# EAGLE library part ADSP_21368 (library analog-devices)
SHARC Processor Auto generated by make-symbol-device-package-bsdl.ulp Rev. 33 Source: 78445023821368_256ballSBGA_bsdl_PrA_0206.txt http://www.analog.com/static/imported-files/data_sheets/ADSP-21367_21368_21369.pdf
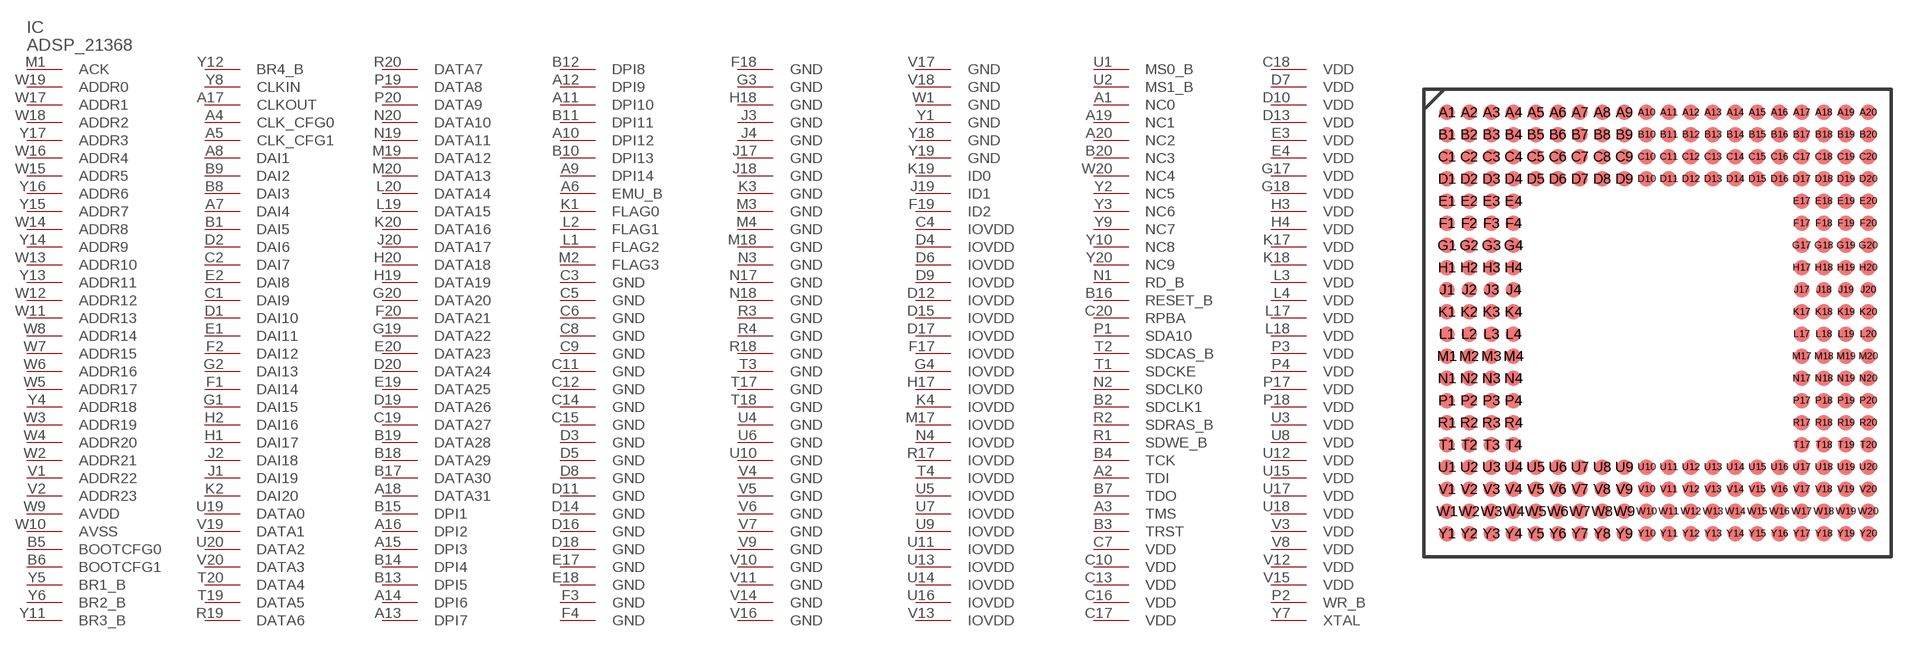
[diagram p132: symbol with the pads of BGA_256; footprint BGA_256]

Designator prefix IC

## ADSP_21368 (OC_FARNELL: 1776206; OC_NEWARK: unknown)  [BGA_256]
A1  NC0  pas
A2  TDI  in
A3  TMS  in
A4  CLK_CFG0  in
A5  CLK_CFG1  in
A6  EMU_B  out
A7  DAI4
A8  DAI1
A9  DPI14
A10  DPI12
A11  DPI10
A12  DPI9
A13  DPI7
A14  DPI6
A15  DPI3
A16  DPI2
A17  CLKOUT  out
A18  DATA31
A19  NC1  pas
A20  NC2  pas
B1  DAI5
B2  SDCLK1
B3  TRST  in
B4  TCK  in
B5  BOOTCFG0  in
B6  BOOTCFG1  in
B7  TDO  out
B8  DAI3
B9  DAI2
B10  DPI13
B11  DPI11
B12  DPI8
B13  DPI5
B14  DPI4
B15  DPI1
B16  RESET_B  in
B17  DATA30
B18  DATA29
B19  DATA28
B20  NC3  pas
C1  DAI9
C2  DAI7
C3  GND  pwr
C4  IOVDD  pwr
C5  GND  pwr
C6  GND  pwr
C7  VDD  pwr
C8  GND  pwr
C9  GND  pwr
C10  VDD  pwr
C11  GND  pwr
C12  GND  pwr
C13  VDD  pwr
C14  GND  pwr
C15  GND  pwr
C16  VDD  pwr
C17  VDD  pwr
C18  VDD  pwr
C19  DATA27
C20  RPBA  in
D1  DAI10
D2  DAI6
D3  GND  pwr
D4  IOVDD  pwr
D5  GND  pwr
D6  IOVDD  pwr
D7  VDD  pwr
D8  GND  pwr
D9  IOVDD  pwr
D10  VDD  pwr
D11  GND  pwr
D12  IOVDD  pwr
D13  VDD  pwr
D14  GND  pwr
D15  IOVDD  pwr
D16  GND  pwr
D17  IOVDD  pwr
D18  GND  pwr
D19  DATA26
D20  DATA24
E1  DAI11
E2  DAI8
E3  VDD  pwr
E4  VDD  pwr
E17  GND  pwr
E18  GND  pwr
E19  DATA25
E20  DATA23
F1  DAI14
F2  DAI12
F3  GND  pwr
F4  GND  pwr
F17  IOVDD  pwr
F18  GND  pwr
F19  ID2  in
F20  DATA21
G1  DAI15
G2  DAI13
G3  GND  pwr
G4  IOVDD  pwr
G17  VDD  pwr
G18  VDD  pwr
G19  DATA22
G20  DATA20
H1  DAI17
H2  DAI16
H3  VDD  pwr
H4  VDD  pwr
H17  IOVDD  pwr
H18  GND  pwr
H19  DATA19
H20  DATA18
J1  DAI19
J2  DAI18
J3  GND  pwr
J4  GND  pwr
J17  GND  pwr
J18  GND  pwr
J19  ID1  in
J20  DATA17
K1  FLAG0
K2  DAI20
K3  GND  pwr
K4  IOVDD  pwr
K17  VDD  pwr
K18  VDD  pwr
K19  ID0  in
K20  DATA16
L1  FLAG2
L2  FLAG1
L3  VDD  pwr
L4  VDD  pwr
L17  VDD  pwr
L18  VDD  pwr
L19  DATA15
L20  DATA14
M1  ACK  in
M2  FLAG3
M3  GND  pwr
M4  GND  pwr
M17  IOVDD  pwr
M18  GND  pwr
M19  DATA12
M20  DATA13
N1  RD_B  out
N2  SDCLK0
N3  GND  pwr
N4  IOVDD  pwr
N17  GND  pwr
N18  GND  pwr
N19  DATA11
N20  DATA10
P1  SDA10  out
P2  WR_B  out
P3  VDD  pwr
P4  VDD  pwr
P17  VDD  pwr
P18  VDD  pwr
P19  DATA8
P20  DATA9
R1  SDWE_B  out
R2  SDRAS_B  out
R3  GND  pwr
R4  GND  pwr
R17  IOVDD  pwr
R18  GND  pwr
R19  DATA6
R20  DATA7
T1  SDCKE  out
T2  SDCAS_B  out
T3  GND  pwr
T4  IOVDD  pwr
T17  GND  pwr
T18  GND  pwr
T19  DATA5
T20  DATA4
U1  MS0_B  out
U2  MS1_B  out
U3  VDD  pwr
U4  GND  pwr
U5  IOVDD  pwr
U6  GND  pwr
U7  IOVDD  pwr
U8  VDD  pwr
U9  IOVDD  pwr
U10  GND  pwr
U11  IOVDD  pwr
U12  VDD  pwr
U13  IOVDD  pwr
U14  IOVDD  pwr
U15  VDD  pwr
U16  IOVDD  pwr
U17  VDD  pwr
U18  VDD  pwr
U19  DATA0
U20  DATA2
V1  ADDR22  out
V2  ADDR23  out
V3  VDD  pwr
V4  GND  pwr
V5  GND  pwr
V6  GND  pwr
V7  GND  pwr
V8  VDD  pwr
V9  GND  pwr
V10  GND  pwr
V11  GND  pwr
V12  VDD  pwr
V13  IOVDD  pwr
V14  GND  pwr
V15  VDD  pwr
V16  GND  pwr
V17  GND  pwr
V18  GND  pwr
V19  DATA1
V20  DATA3
W1  GND  pwr
W2  ADDR21  out
W3  ADDR19  out
W4  ADDR20  out
W5  ADDR17  out
W6  ADDR16  out
W7  ADDR15  out
W8  ADDR14  out
W9  AVDD  pwr
W10  AVSS  pwr
W11  ADDR13  out
W12  ADDR12  out
W13  ADDR10  out
W14  ADDR8  out
W15  ADDR5  out
W16  ADDR4  out
W17  ADDR1  out
W18  ADDR2  out
W19  ADDR0  out
W20  NC4  pas
Y1  GND  pwr
Y2  NC5  pas
Y3  NC6  pas
Y4  ADDR18  out
Y5  BR1_B
Y6  BR2_B
Y7  XTAL  out
Y8  CLKIN  in
Y9  NC7  pas
Y10  NC8  pas
Y11  BR3_B
Y12  BR4_B
Y13  ADDR11  out
Y14  ADDR9  out
Y15  ADDR7  out
Y16  ADDR6  out
Y17  ADDR3  out
Y18  GND  pwr
Y19  GND  pwr
Y20  NC9  pas

## Footprint BGA_256 (pad centres in mm)
256-Ball Ball Grid Array, Thermally Enhanced BGA_ED Auto generated by make-symbol-device-package-bsdl.ulp Rev. 33 Source: 78445023821368_256ballSBGA_bsdl_PrA_0206.txt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
smd 0.9 x 0.9: A1 -12.065,12.065; A2 -10.795,12.065; A3 -9.525,12.065; A4 -8.255,12.065; A5 -6.985,12.065; A6 -5.715,12.065; A7 -4.445,12.065; A8 -3.175,12.065; A9 -1.905,12.065; A10 -0.635,12.065; A11 0.635,12.065; A12 1.905,12.065; A13 3.175,12.065; A14 4.445,12.065; A15 5.715,12.065; A16 6.985,12.065; A17 8.255,12.065; A18 9.525,12.065; A19 10.795,12.065; A20 12.065,12.065; B1 -12.065,10.795; B2 -10.795,10.795; B3 -9.525,10.795; B4 -8.255,10.795; B5 -6.985,10.795; B6 -5.715,10.795; B7 -4.445,10.795; B8 -3.175,10.795; B9 -1.905,10.795; B10 -0.635,10.795; B11 0.635,10.795; B12 1.905,10.795; B13 3.175,10.795; B14 4.445,10.795; B15 5.715,10.795; B16 6.985,10.795; B17 8.255,10.795; B18 9.525,10.795; B19 10.795,10.795; B20 12.065,10.795; C1 -12.065,9.525; C2 -10.795,9.525; C3 -9.525,9.525; C4 -8.255,9.525; C5 -6.985,9.525; C6 -5.715,9.525; C7 -4.445,9.525; C8 -3.175,9.525; C9 -1.905,9.525; C10 -0.635,9.525; C11 0.635,9.525; C12 1.905,9.525; C13 3.175,9.525; C14 4.445,9.525; C15 5.715,9.525; C16 6.985,9.525; C17 8.255,9.525; C18 9.525,9.525; C19 10.795,9.525; C20 12.065,9.525; D1 -12.065,8.255; D2 -10.795,8.255; D3 -9.525,8.255; D4 -8.255,8.255; D5 -6.985,8.255; D6 -5.715,8.255; D7 -4.445,8.255; D8 -3.175,8.255; D9 -1.905,8.255; D10 -0.635,8.255; D11 0.635,8.255; D12 1.905,8.255; D13 3.175,8.255; D14 4.445,8.255; D15 5.715,8.255; D16 6.985,8.255; D17 8.255,8.255; D18 9.525,8.255; D19 10.795,8.255; D20 12.065,8.255; E1 -12.065,6.985; E2 -10.795,6.985; E3 -9.525,6.985; E4 -8.255,6.985; E17 8.255,6.985; E18 9.525,6.985; E19 10.795,6.985; E20 12.065,6.985; F1 -12.065,5.715; F2 -10.795,5.715; F3 -9.525,5.715; F4 -8.255,5.715; F17 8.255,5.715; F18 9.525,5.715; F19 10.795,5.715; F20 12.065,5.715; G1 -12.065,4.445; G2 -10.795,4.445; G3 -9.525,4.445; G4 -8.255,4.445; G17 8.255,4.445; G18 9.525,4.445; G19 10.795,4.445; G20 12.065,4.445; H1 -12.065,3.175; H2 -10.795,3.175; H3 -9.525,3.175; H4 -8.255,3.175; H17 8.255,3.175; H18 9.525,3.175; H19 10.795,3.175; H20 12.065,3.175; J1 -12.065,1.905; J2 -10.795,1.905; J3 -9.525,1.905; J4 -8.255,1.905; J17 8.255,1.905; J18 9.525,1.905; J19 10.795,1.905; J20 12.065,1.905; K1 -12.065,0.635; K2 -10.795,0.635; K3 -9.525,0.635; K4 -8.255,0.635; K17 8.255,0.635; K18 9.525,0.635; K19 10.795,0.635; K20 12.065,0.635; L1 -12.065,-0.635; L2 -10.795,-0.635; L3 -9.525,-0.635; L4 -8.255,-0.635; L17 8.255,-0.635; L18 9.525,-0.635; L19 10.795,-0.635; L20 12.065,-0.635; M1 -12.065,-1.905; M2 -10.795,-1.905; M3 -9.525,-1.905; M4 -8.255,-1.905; M17 8.255,-1.905; M18 9.525,-1.905; M19 10.795,-1.905; M20 12.065,-1.905; N1 -12.065,-3.175; N2 -10.795,-3.175; N3 -9.525,-3.175; N4 -8.255,-3.175; N17 8.255,-3.175; N18 9.525,-3.175; N19 10.795,-3.175; N20 12.065,-3.175; P1 -12.065,-4.445; P2 -10.795,-4.445; P3 -9.525,-4.445; P4 -8.255,-4.445; P17 8.255,-4.445; P18 9.525,-4.445; P19 10.795,-4.445; P20 12.065,-4.445; R1 -12.065,-5.715; R2 -10.795,-5.715; R3 -9.525,-5.715; R4 -8.255,-5.715; R17 8.255,-5.715; R18 9.525,-5.715; R19 10.795,-5.715; R20 12.065,-5.715; T1 -12.065,-6.985; T2 -10.795,-6.985; T3 -9.525,-6.985; T4 -8.255,-6.985; T17 8.255,-6.985; T18 9.525,-6.985; T19 10.795,-6.985; T20 12.065,-6.985; U1 -12.065,-8.255; U2 -10.795,-8.255; U3 -9.525,-8.255; U4 -8.255,-8.255; U5 -6.985,-8.255; U6 -5.715,-8.255; U7 -4.445,-8.255; U8 -3.175,-8.255; U9 -1.905,-8.255; U10 -0.635,-8.255; U11 0.635,-8.255; U12 1.905,-8.255; U13 3.175,-8.255; U14 4.445,-8.255; U15 5.715,-8.255; U16 6.985,-8.255; U17 8.255,-8.255; U18 9.525,-8.255; U19 10.795,-8.255; U20 12.065,-8.255; V1 -12.065,-9.525; V2 -10.795,-9.525; V3 -9.525,-9.525; V4 -8.255,-9.525; V5 -6.985,-9.525; V6 -5.715,-9.525; V7 -4.445,-9.525; V8 -3.175,-9.525; V9 -1.905,-9.525; V10 -0.635,-9.525; V11 0.635,-9.525; V12 1.905,-9.525; V13 3.175,-9.525; V14 4.445,-9.525; V15 5.715,-9.525; V16 6.985,-9.525; V17 8.255,-9.525; V18 9.525,-9.525; V19 10.795,-9.525; V20 12.065,-9.525; W1 -12.065,-10.795; W2 -10.795,-10.795; W3 -9.525,-10.795; W4 -8.255,-10.795; W5 -6.985,-10.795; W6 -5.715,-10.795; W7 -4.445,-10.795; W8 -3.175,-10.795; W9 -1.905,-10.795; W10 -0.635,-10.795; W11 0.635,-10.795; W12 1.905,-10.795; W13 3.175,-10.795; W14 4.445,-10.795; W15 5.715,-10.795; W16 6.985,-10.795; W17 8.255,-10.795; W18 9.525,-10.795; W19 10.795,-10.795; W20 12.065,-10.795; Y1 -12.065,-12.065; Y2 -10.795,-12.065; Y3 -9.525,-12.065; Y4 -8.255,-12.065; Y5 -6.985,-12.065; Y6 -5.715,-12.065; Y7 -4.445,-12.065; Y8 -3.175,-12.065; Y9 -1.905,-12.065; Y10 -0.635,-12.065; Y11 0.635,-12.065; Y12 1.905,-12.065; Y13 3.175,-12.065; Y14 4.445,-12.065; Y15 5.715,-12.065; Y16 6.985,-12.065; Y17 8.255,-12.065; Y18 9.525,-12.065; Y19 10.795,-12.065; Y20 12.065,-12.065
